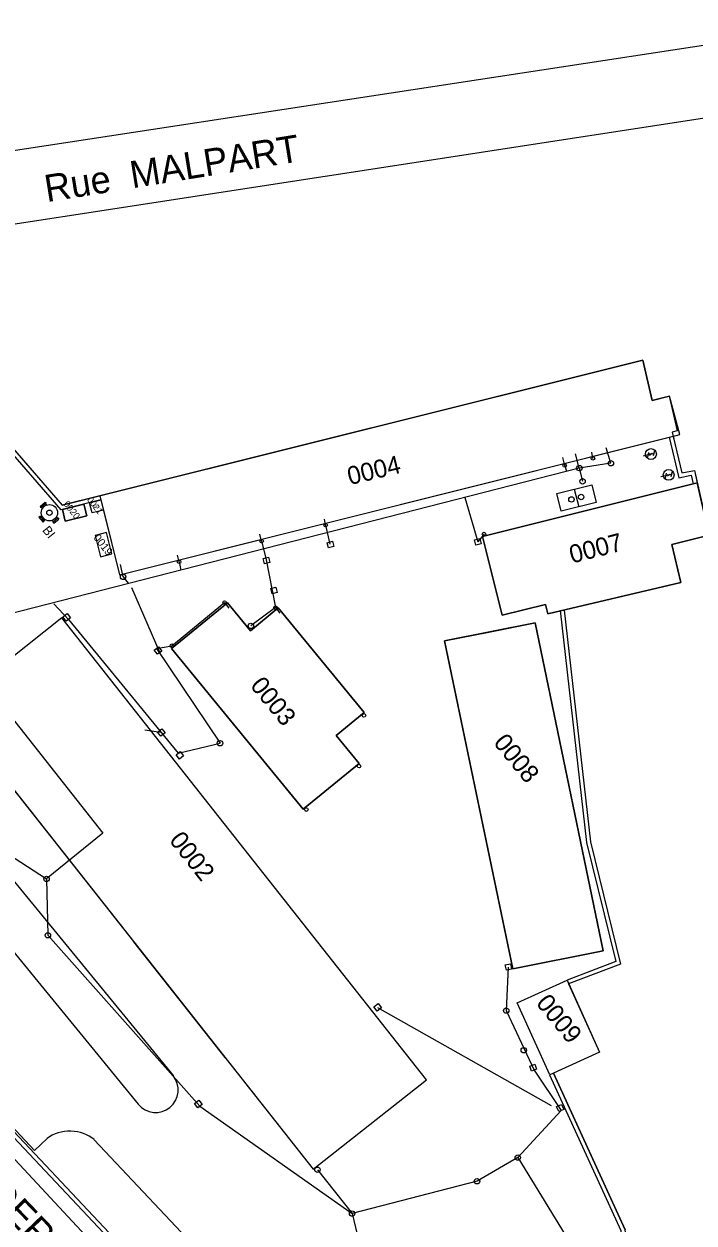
# Model space of a CAD drawing. Extents: x 704421 to 705059, y 7058908 to 7059523.
# Drawn here: x 704507.1 to 704581.3, y 7058975.5 to 7059108.3 of the extents above; entities that cross this region are included whole.
import ezdxf

# ---------------------------------------------------------------- set-up
doc = ezdxf.new("R2010")
doc.units = 0
for name, color, linetype in [('DH_HACHURE-MOTIF', 7, 'Continuous'), ('DH_TEXTE', 7, 'Continuous'), ('GEOSID_AIRE_AMENAGEE_NUMERO', 7, 'Continuous'), ('GEOSID_AIRE_AMENAGEE_POLYGONE', 7, 'Continuous'), ('GO_A DEMOLIR', 7, 'Continuous'), ('GO_DALLE', 7, 'Continuous'), ('GO_MUR_EXTERIEUR', 7, 'Continuous'), ('IMM_LIMITE PHYSIQUE', 7, 'Continuous'), ('R_PLU_CANALISATION_CL_A', 7, 'Continuous'), ('RES_EAU BASSE PRESSION', 7, 'Continuous'), ('RES_EAU BASSE PRESSION - EQUIP - TEXTE', 7, 'Continuous'), ('RES_INCENDIE - EQUIP - TEXTE', 7, 'Continuous'), ('SID_NUMERO_BATI', 7, 'Continuous'), ('SID_POLYLIGNES_BATI', 7, 'Continuous'), ('SID_POLYLIGNES_IMMEUBLE', 7, 'Continuous'), ('SO_EP_EQUIP', 7, 'Continuous'), ('VOIRIE_BORDURE', 7, 'Continuous'), ('VOIRIE_ROUTE', 7, 'Continuous')]:
    doc.layers.add(name, color=color, linetype=linetype)

msp = doc.modelspace()

# ---------------------------------------------------------------- linework, layer by layer
at = {"layer": 'DH_HACHURE-MOTIF'}
for p, q in [((704553.67, 7059039.96), (704558.58, 7059040.92)), ((704561.21, 7059003.63), (704553.67, 7059039.96)), ((704571.23, 7059005.64), (704561.21, 7059003.63)), ((704561.7, 7058999.87), (704567.23, 7059002.37)), ((704565.31, 7058991.89), (704561.7, 7058999.87)), ((704570.84, 7058994.39), (704565.31, 7058991.89))]:
    msp.add_line(p, q, dxfattribs=at)
for points in [[(704515.58, 7059055.6), (704515.87, 7059054.46), (704517.65, 7059047.3), (704579.31, 7059062.71), (704579.74, 7059062.82), (704578.59, 7059067.1), (704576.65, 7059066.62), (704575.62, 7059071.07), (704538.76, 7059061.85), (704515.47, 7059056.03), (704515.58, 7059055.6)], [(704564.85, 7059044.01), (704565.09, 7059042.95), (704579.84, 7059046.44), (704578.84, 7059050.66), (704582.98, 7059051.69), (704581.66, 7059057.48), (704581.22, 7059057.37), (704557.88, 7059051.53), (704560.06, 7059042.8), (704564.85, 7059044.01)], [(704513.69, 7059055.12), (704511.31, 7059054.53), (704511.63, 7059053.24), (704514.01, 7059053.83), (704513.69, 7059055.12)], [(704515.52, 7059049.28), (704516.81, 7059049.61), (704516.22, 7059051.98), (704514.93, 7059051.66), (704515.52, 7059049.28)], [(704532.15, 7059041.09), (704529.61, 7059044.18), (704523.42, 7059039.11), (704538, 7059021.32), (704544.19, 7059026.39), (704541.65, 7059029.48), (704544.75, 7059032.02), (704535.24, 7059043.62), (704532.15, 7059041.09)], [(704551.65, 7058991.33), (704511.27, 7059042.51), (704505.27, 7059037.77), (704505.89, 7059036.98), (704499.33, 7059031.81), (704539.09, 7058981.42), (704551.65, 7058991.33)], [(704558.58, 7059040.92), (704563.69, 7059041.98), (704571.23, 7059005.64)], [(704567.23, 7059002.37), (704567.32, 7059002.18), (704570.84, 7058994.39)]]:
    msp.add_lwpolyline(points, dxfattribs=at)
at = {"layer": 'GEOSID_AIRE_AMENAGEE_POLYGONE'}
msp.add_lwpolyline([(704514.6, 7059054.14), (704514.32, 7059055.28), (704515.58, 7059055.6), (704515.86, 7059054.46)], close=True, dxfattribs=at)
at = {"layer": 'GO_A DEMOLIR'}
for points in [[(704513.69, 7059055.12), (704514.01, 7059053.83), (704511.63, 7059053.24), (704511.31, 7059054.53)], [(704516.22, 7059051.98), (704514.93, 7059051.66), (704515.52, 7059049.28), (704516.81, 7059049.61)], [(704563.69, 7059041.98), (704553.67, 7059039.96), (704561.21, 7059003.63), (704571.23, 7059005.64)]]:
    msp.add_lwpolyline(points, close=True, dxfattribs=at)
at = {"layer": 'GO_DALLE'}
msp.add_lwpolyline([(704515.58, 7059055.6), (704515.87, 7059054.46), (704514.6, 7059054.14), (704514.32, 7059055.28)], close=True, dxfattribs=at)
at = {"layer": 'GO_MUR_EXTERIEUR'}
for p, q in [((704575.62, 7059071.07), (704515.47, 7059056.03)), ((704576.65, 7059066.62), (704575.62, 7059071.07)), ((704578.59, 7059067.1), (704576.65, 7059066.62)), ((704579.74, 7059062.82), (704578.59, 7059067.1)), ((704517.65, 7059047.3), (704579.74, 7059062.82)), ((704557.88, 7059051.53), (704581.66, 7059057.48)), ((704515.47, 7059056.03), (704517.65, 7059047.3)), ((704560.06, 7059042.8), (704557.88, 7059051.53)), ((704582.98, 7059051.69), (704578.84, 7059050.66)), ((704578.84, 7059050.66), (704579.84, 7059046.44)), ((704523.42, 7059039.11), (704529.61, 7059044.18)), ((704529.61, 7059044.18), (704532.15, 7059041.09)), ((704532.15, 7059041.09), (704535.24, 7059043.62)), ((704535.24, 7059043.62), (704544.75, 7059032.02)), ((704511.27, 7059042.51), (704505.27, 7059037.77)), ((704551.65, 7058991.33), (704511.27, 7059042.51)), ((704553.67, 7059039.96), (704563.69, 7059041.98)), ((704563.69, 7059041.98), (704571.23, 7059005.64)), ((704561.21, 7059003.63), (704553.67, 7059039.96)), ((704538, 7059021.32), (704523.42, 7059039.11)), ((704544.75, 7059032.02), (704541.65, 7059029.48)), ((704499.33, 7059031.81), (704539.09, 7058981.42)), ((704541.65, 7059029.48), (704544.19, 7059026.39)), ((704544.19, 7059026.39), (704538, 7059021.32)), ((704571.23, 7059005.64), (704561.21, 7059003.63)), ((704561.7, 7058999.87), (704567.23, 7059002.37)), ((704567.23, 7059002.37), (704570.84, 7058994.39)), ((704565.31, 7058991.89), (704561.7, 7058999.87)), ((704570.84, 7058994.39), (704565.31, 7058991.89)), ((704539.09, 7058981.42), (704551.65, 7058991.33))]:
    msp.add_line(p, q, dxfattribs=at)
for points in [[(704511.31, 7059054.53), (704511.63, 7059053.24), (704514.01, 7059053.83), (704513.69, 7059055.12)], [(704516.22, 7059051.98), (704514.93, 7059051.66), (704515.52, 7059049.28), (704516.81, 7059049.61)]]:
    msp.add_lwpolyline(points, close=True, dxfattribs=at)
msp.add_lwpolyline([(704579.84, 7059046.44), (704565.09, 7059042.95), (704564.85, 7059044.01), (704560.06, 7059042.8)], dxfattribs=at)
at = {"layer": 'IMM_LIMITE PHYSIQUE'}
for p, q in [((704499.39, 7059068.01), (704511.13, 7059054.48)), ((704499.74, 7059068.3), (704511.28, 7059054.99)), ((704515.47, 7059056.03), (704511.28, 7059054.99)), ((704515.59, 7059055.6), (704511.13, 7059054.48)), ((704472.28, 7059020.59), (704535.98, 7058953.07)), ((704472.61, 7059020.9), (704536.21, 7058953.48))]:
    msp.add_line(p, q, dxfattribs=at)
for points in [[(704578.99, 7059062.63), (704579.94, 7059058.58), (704581.34, 7059058.85), (704581.66, 7059057.48)], [(704578.55, 7059062.53), (704579.6, 7059058.05), (704581, 7059058.32), (704581.22, 7059057.38)], [(704566.47, 7059043.33), (704569.4, 7059017.61), (704572.62, 7059004.43), (704567.24, 7059002.38)], [(704566.92, 7059043.38), (704569.84, 7059017.69), (704573.15, 7059004.16), (704567.4, 7059001.96)], [(704574.25, 7058967.23), (704573.22, 7058974.58), (704565.32, 7058991.86)], [(704574.7, 7058967.3), (704573.66, 7058974.71), (704565.73, 7058992.05)]]:
    msp.add_lwpolyline(points, dxfattribs=at)
at = {"layer": 'R_PLU_CANALISATION_CL_A'}
for p, q in [((704572.09, 7059059.65), (704571.58, 7059061.35)), ((704566.97, 7059059.41), (704566.75, 7059060.27)), ((704568.59, 7059059.11), (704568.17, 7059060.71)), ((704570.1, 7059060.19), (704569.97, 7059060.88)), ((704566.97, 7059059.41), (704567.18, 7059058.73)), ((704568.59, 7059059.11), (704568.95, 7059057.65)), ((704568.03, 7059056.78), (704568.52, 7059054.84)), ((704555.89, 7059055.85), (704557.33, 7059050.95)), ((704540.48, 7059052.79), (704540.36, 7059053.44)), ((704540.48, 7059052.79), (704540.94, 7059050.67)), ((704533.39, 7059051.02), (704533.2, 7059051.8)), ((704533.39, 7059051.02), (704533.86, 7059049.15)), ((704558.03, 7059051.8), (704557.33, 7059050.95)), ((704524.25, 7059048.73), (704524.06, 7059049.47)), ((704518.04, 7059047.06), (704517.76, 7059048.45)), ((704524.25, 7059048.73), (704524.43, 7059047.8)), ((704518.04, 7059047.06), (704518.59, 7059046.36)), ((704518.96, 7059045.89), (704522.11, 7059038.66)), ((704511.99, 7059042.34), (704510.38, 7059044.06)), ((704529.29, 7059044.21), (704529.77, 7059043.61)), ((704534.93, 7059043.65), (704535.4, 7059043.05)), ((704521.74, 7059039.13), (704528.78, 7059028.63)), ((704522.21, 7059029.8), (704520.44, 7059030.09)), ((704509.56, 7059013.59), (704509.71, 7059007.35)), ((704509.71, 7059007.35), (704526.55, 7058988.4)), ((704519.21, 7059006.61), (704529.33, 7058993.79)), ((704560.7, 7059003.81), (704560.49, 7058999)), ((704546.23, 7058999.35), (704565.49, 7058988.5)), ((704526.55, 7058988.4), (704543.42, 7058976.51)), ((704539.58, 7058981.37), (704543.42, 7058976.51)), ((704543.42, 7058976.51), (704545.68, 7058967.24))]:
    msp.add_line(p, q, dxfattribs=at)
for points in [[(704572.09, 7059059.65), (704568.59, 7059059.11), (704502.04, 7059042.07)], [(704569.97, 7059057.26), (704570.46, 7059055.32), (704566.58, 7059054.35), (704566.09, 7059056.29), (704569.97, 7059057.26)], [(704463.25, 7059054.13), (704485.05, 7059028.64), (704491.95, 7059025.02), (704509.56, 7059013.59)], [(704540.65, 7059050.85), (704541.24, 7059051), (704541.38, 7059050.42), (704540.8, 7059050.27), (704540.65, 7059050.85)], [(704556.99, 7059051.16), (704557.57, 7059051.31), (704557.72, 7059050.73), (704557.14, 7059050.58), (704556.99, 7059051.16)], [(704498.62, 7059048.1), (704494.89, 7059045.16), (704515.8, 7059018.65), (704509.56, 7059013.59)], [(704533.86, 7059049.15), (704534.93, 7059043.65), (704532.2, 7059041.63)], [(704533.57, 7059049.08), (704534.15, 7059049.23), (704534.29, 7059048.64), (704533.71, 7059048.5), (704533.57, 7059049.08)], [(704534.4, 7059045.76), (704534.98, 7059045.91), (704535.12, 7059045.33), (704534.54, 7059045.18), (704534.4, 7059045.76)], [(704521.74, 7059039.13), (704523.45, 7059039.43), (704529.29, 7059044.21)], [(704512.22, 7059042.52), (704511.75, 7059042.15), (704511.38, 7059042.62), (704511.85, 7059042.99), (704512.22, 7059042.52)], [(704511.99, 7059042.34), (704524.15, 7059027.52), (704528.78, 7059028.63)], [(704521.5, 7059038.95), (704521.98, 7059039.32), (704522.34, 7059038.84), (704521.87, 7059038.48), (704521.5, 7059038.95)], [(704522.69, 7059029.77), (704522.22, 7059029.4), (704521.85, 7059029.87), (704522.32, 7059030.24), (704522.69, 7059029.77)], [(704524.75, 7059027.24), (704524.28, 7059026.87), (704523.91, 7059027.34), (704524.38, 7059027.71), (704524.75, 7059027.24)], [(704560.38, 7059004.07), (704560.97, 7059004.2), (704561.09, 7059003.61), (704560.51, 7059003.48), (704560.38, 7059004.07)], [(704560.49, 7058999), (704563.58, 7058992.41), (704566.58, 7058987.94), (704561.77, 7058982.71), (704557.26, 7058980.09), (704543.42, 7058976.51)], [(704546.68, 7058999.31), (704546.21, 7058998.94), (704545.83, 7058999.41), (704546.31, 7058999.78), (704546.68, 7058999.31)], [(704563.09, 7058992.86), (704563.65, 7058993.08), (704563.86, 7058992.52), (704563.3, 7058992.3), (704563.09, 7058992.86)], [(704526.79, 7058988.59), (704526.32, 7058988.21), (704525.94, 7058988.69), (704526.42, 7058989.06), (704526.79, 7058988.59)], [(704566.07, 7058988.37), (704566.62, 7058988.61), (704566.86, 7058988.06), (704566.31, 7058987.82), (704566.07, 7058988.37)], [(704561.77, 7058982.71), (704570.05, 7058969.19), (704573.99, 7058967.43)]]:
    msp.add_lwpolyline(points, dxfattribs=at)
for centre, radius in [((704576.53, 7059060.67), 0.6), ((704572.09, 7059059.65), 0.3), ((704568.59, 7059059.11), 0.3), ((704578.49, 7059058.36), 0.6), ((704568.95, 7059057.65), 0.3), ((704567.72, 7059055.64), 0.3), ((704568.79, 7059055.91), 0.3), ((704518.04, 7059047.06), 0.3), ((704532.2, 7059041.63), 0.3), ((704528.78, 7059028.63), 0.3), ((704509.56, 7059013.59), 0.3), ((704509.71, 7059007.35), 0.3), ((704560.49, 7058999), 0.3), ((704562.44, 7058994.61), 0.3), ((704561.77, 7058982.71), 0.3), ((704539.58, 7058981.37), 0.3), ((704557.26, 7058980.09), 0.3), ((704543.42, 7058976.51), 0.3)]:
    msp.add_circle(centre, radius, dxfattribs=at)
at = {"layer": 'RES_EAU BASSE PRESSION'}
for p, q in [((704576.37, 7059060.63), (704576.2, 7059060.58)), ((704576.92, 7059061.02), (704576.78, 7059060.47)), ((704578.88, 7059058.71), (704578.74, 7059058.16)), ((704578.33, 7059058.32), (704578.16, 7059058.27))]:
    msp.add_line(p, q, dxfattribs=at)
at = {"layer": 'RES_EAU BASSE PRESSION - EQUIP - TEXTE'}
for p, q in [((704576.2, 7059060.58), (704575.65, 7059060.44)), ((704576.38, 7059060.56), (704576.35, 7059060.69)), ((704576.7, 7059060.64), (704576.35, 7059060.69)), ((704576.38, 7059060.56), (704576.67, 7059060.77)), ((704576.7, 7059060.64), (704576.67, 7059060.77)), ((704576.69, 7059060.7), (704576.85, 7059060.75)), ((704578.16, 7059058.27), (704577.61, 7059058.13)), ((704578.35, 7059058.25), (704578.31, 7059058.38)), ((704578.66, 7059058.33), (704578.31, 7059058.38)), ((704578.35, 7059058.25), (704578.63, 7059058.46)), ((704578.66, 7059058.33), (704578.63, 7059058.46)), ((704578.65, 7059058.39), (704578.81, 7059058.44))]:
    msp.add_line(p, q, dxfattribs=at)
at = {"layer": 'RES_INCENDIE - EQUIP - TEXTE'}
for p, q in [((704576.27, 7059060.86), (704576.13, 7059060.31)), ((704578.23, 7059058.55), (704578.09, 7059058)), ((704508.84, 7059054.87), (704509.4, 7059055.33)), ((704508.84, 7059054.87), (704508.93, 7059054.76)), ((704508.93, 7059054.76), (704509.49, 7059055.21)), ((704508.98, 7059054.8), (704509.11, 7059054.64)), ((704509.4, 7059055.33), (704509.49, 7059055.21)), ((704509.44, 7059055.18), (704509.57, 7059055.02)), ((704508.72, 7059053.69), (704508.84, 7059053.79)), ((704508.72, 7059053.69), (704509.18, 7059053.13)), ((704508.84, 7059053.79), (704509.29, 7059053.23)), ((704508.87, 7059053.74), (704509.03, 7059053.87)), ((704509.26, 7059053.28), (704509.41, 7059053.4)), ((704510.18, 7059053.33), (704510.31, 7059053.17)), ((704510.26, 7059053.13), (704510.82, 7059053.59)), ((704510.36, 7059053.02), (704510.92, 7059053.47)), ((704510.65, 7059053.71), (704510.77, 7059053.55)), ((704510.82, 7059053.59), (704510.92, 7059053.47)), ((704509.18, 7059053.13), (704509.29, 7059053.23)), ((704510.26, 7059053.13), (704510.36, 7059053.02))]:
    msp.add_line(p, q, dxfattribs=at)
for radius in [0.9, 0.3]:
    msp.add_circle((704509.88, 7059054.17), radius, dxfattribs=at)
at = {"layer": 'SID_POLYLIGNES_BATI'}
for p, q in [((704575.62, 7059071.07), (704515.47, 7059056.03)), ((704576.65, 7059066.62), (704575.62, 7059071.07)), ((704578.59, 7059067.1), (704576.65, 7059066.62)), ((704579.74, 7059062.82), (704578.59, 7059067.1)), ((704517.65, 7059047.3), (704579.74, 7059062.82)), ((704515.47, 7059056.03), (704517.65, 7059047.3)), ((704523.42, 7059039.11), (704529.61, 7059044.18)), ((704529.61, 7059044.18), (704532.15, 7059041.09)), ((704532.15, 7059041.09), (704535.24, 7059043.62)), ((704535.24, 7059043.62), (704544.75, 7059032.02)), ((704511.27, 7059042.51), (704505.27, 7059037.77)), ((704551.65, 7058991.33), (704511.27, 7059042.51)), ((704553.67, 7059039.96), (704563.69, 7059041.98)), ((704563.69, 7059041.98), (704571.23, 7059005.64)), ((704561.21, 7059003.63), (704553.67, 7059039.96)), ((704538, 7059021.32), (704523.42, 7059039.11)), ((704544.75, 7059032.02), (704541.65, 7059029.48)), ((704499.33, 7059031.81), (704539.09, 7058981.42)), ((704541.65, 7059029.48), (704544.19, 7059026.39)), ((704544.19, 7059026.39), (704538, 7059021.32)), ((704571.23, 7059005.64), (704561.21, 7059003.63)), ((704561.7, 7058999.87), (704567.23, 7059002.37)), ((704567.23, 7059002.37), (704570.84, 7058994.39)), ((704565.31, 7058991.89), (704561.7, 7058999.87)), ((704570.84, 7058994.39), (704565.31, 7058991.89)), ((704539.09, 7058981.42), (704551.65, 7058991.33))]:
    msp.add_line(p, q, dxfattribs=at)
for points in [[(704511.31, 7059054.53), (704511.63, 7059053.24), (704514.01, 7059053.83), (704513.69, 7059055.12)], [(704514.6, 7059054.14), (704514.32, 7059055.28), (704515.58, 7059055.6), (704515.87, 7059054.46)], [(704516.22, 7059051.98), (704514.93, 7059051.66), (704515.52, 7059049.28), (704516.81, 7059049.61)]]:
    msp.add_lwpolyline(points, close=True, dxfattribs=at)
at = {"layer": 'SID_POLYLIGNES_IMMEUBLE'}
for p, q in [((704511.28, 7059054.99), (704575.62, 7059071.07)), ((704575.62, 7059071.07), (704576.65, 7059066.62)), ((704576.65, 7059066.62), (704578.55, 7059067.1)), ((704511.28, 7059054.99), (704511.28, 7059054.99)), ((704582.98, 7059051.69), (704578.84, 7059050.66)), ((704578.84, 7059050.66), (704579.84, 7059046.44)), ((704535.98, 7058953.07), (704446.77, 7059047.64)), ((704579.84, 7059046.44), (704566.92, 7059043.39)), ((704573.15, 7059004.16), (704567.4, 7059001.96)), ((704567.4, 7059001.96), (704570.84, 7058994.39)), ((704570.84, 7058994.39), (704565.73, 7058992.05)), ((704565.73, 7058992.05), (704573.66, 7058974.71))]:
    msp.add_line(p, q, dxfattribs=at)
for points in [[(704492.42, 7059080.39), (704493.18, 7059075.86), (704511.28, 7059054.99)], [(704578.55, 7059067.1), (704579.45, 7059063.26), (704578.88, 7059063.11), (704579.94, 7059058.58), (704581.34, 7059058.85), (704582.98, 7059051.69)], [(704566.92, 7059043.39), (704569.84, 7059017.69), (704573.15, 7059004.16)]]:
    msp.add_lwpolyline(points, dxfattribs=at)
at = {"layer": 'SO_EP_EQUIP'}
for centre in [(704570.1, 7059060.19), (704566.97, 7059059.41), (704540.48, 7059052.79), (704558.03, 7059051.8), (704533.39, 7059051.02), (704524.25, 7059048.73), (704529.29, 7059044.21), (704534.93, 7059043.65), (704523.45, 7059039.43), (704544.73, 7059031.71), (704544.18, 7059026.09), (704538.34, 7059021.28)]:
    msp.add_circle(centre, 0.2, dxfattribs=at)
at = {"layer": 'VOIRIE_BORDURE'}
for p, q in [((704504.13, 7059015.53), (704523.58, 7058991.8)), ((704500.26, 7059012.37), (704519.71, 7058988.63)), ((704490.3, 7059002.52), (704508.23, 7058983.51)), ((704508.23, 7058983.51), (704509.63, 7058984.82)), ((704514.85, 7058984.67), (704525.12, 7058973.78))]:
    msp.add_line(p, q, dxfattribs=at)
msp.add_arc((704521.65, 7058990.21), 2.5, 219.3307, 39.3307, dxfattribs=at)
msp.add_ellipse((704512.15, 7058982.64), major_axis=(-3.68, 0), ratio=0.816097, start_param=3.897855, end_param=5.468654, dxfattribs=at)
at = {"layer": 'VOIRIE_ROUTE'}
msp.add_line((704482.54, 7059007.66), (704534.87, 7058951.59), dxfattribs=at)
for points in [[(704439.21, 7059062.29), (704466.43, 7059084.66), (704472.47, 7059087.95), (704480.92, 7059090.49), (704597.81, 7059108.33)], [(704599.06, 7059100.45), (704481.77, 7059082.41), (704472.42, 7059078.45), (704444.83, 7059056.07)]]:
    msp.add_lwpolyline(points, dxfattribs=at)

# ---------------------------------------------------------------- texts
at = {"layer": 'DH_TEXTE'}
for s, rotation, p in [('Rue  MALPART', 9.1668, (704509.59, 7059088.58)), ('Rue LYDERIC', 313.8024, (704493.48, 7058988.15))]:
    msp.add_text(s, height=3, rotation=rotation, dxfattribs=at).set_placement(p)
at = {"layer": 'GEOSID_AIRE_AMENAGEE_NUMERO'}
msp.add_text('0021', height=0.225, rotation=8.0308, dxfattribs=at).set_placement((704514.68, 7059054.79))
at = {"layer": 'RES_INCENDIE - EQUIP - TEXTE'}
msp.add_text('BI', height=1, rotation=308.2727, dxfattribs=at).set_placement((704509.04, 7059052.21))
at = {"layer": 'SID_NUMERO_BATI'}
for s, height, rotation, p in [('0004', 2, 13.5243, (704543.16, 7059057.22)), ('0021', 0.702, 308.0308, (704514.01, 7059055.58)), ('0020', 0.738, 308.0308, (704511.4, 7059055.12)), ('0007', 2, 14.5051, (704567.78, 7059048.53)), ('0019', 0.866, 308.0308, (704514.7, 7059051.37)), ('0003', 2, 309.3307, (704532.04, 7059034.97)), ('0008', 2, 309.3307, (704558.99, 7059028.65)), ('0002', 2, 308.2727, (704523.07, 7059017.85)), ('0009', 2, 309.3307, (704563.71, 7058999.79))]:
    msp.add_text(s, height=height, rotation=rotation, dxfattribs=at).set_placement(p)

doc.saveas('drawing.dxf')
